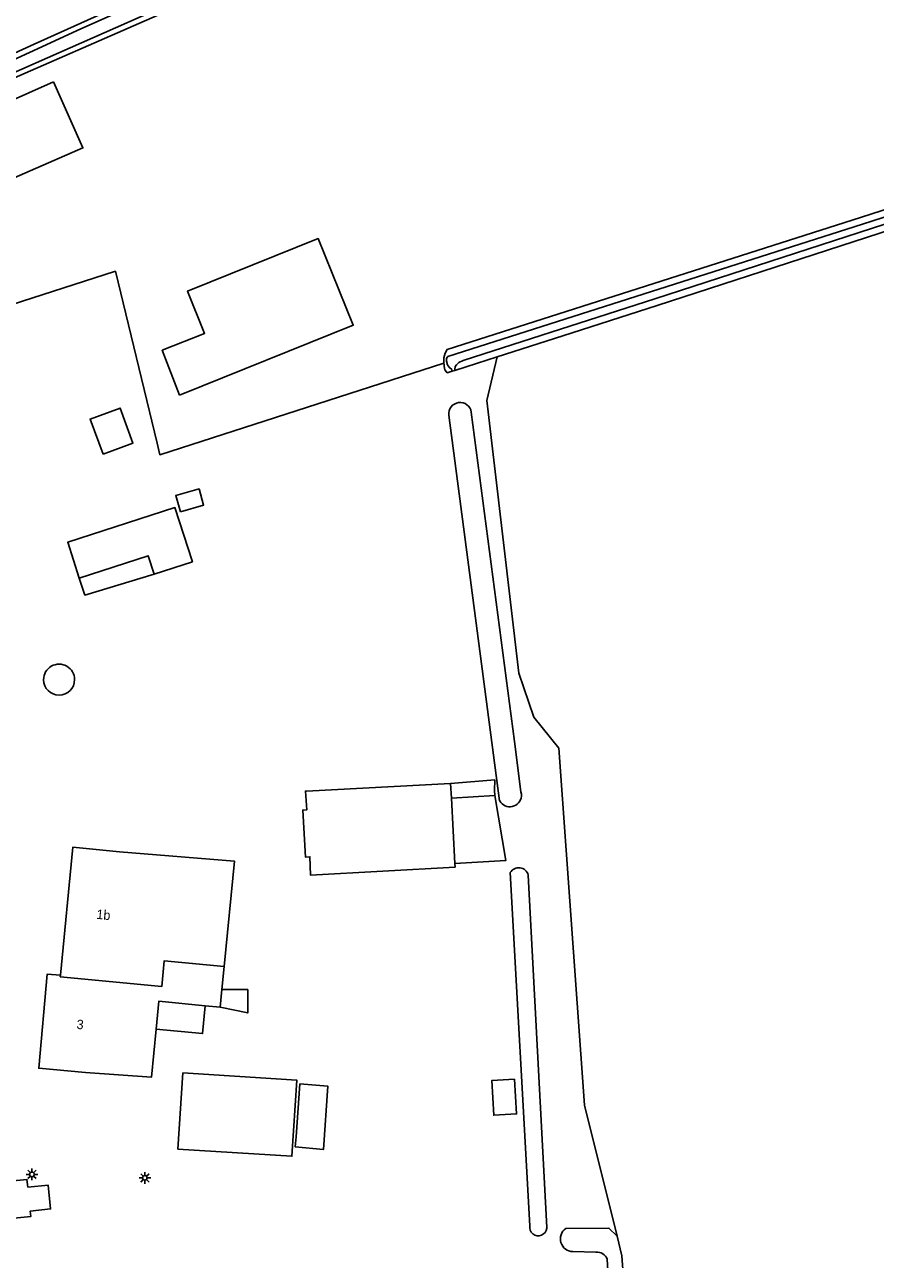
# Model space of a CAD drawing. Extents: x 140000 to 143000, y 403500 to 406000.
# Drawn here: x 140561.8 to 140652.7, y 404354.5 to 404486.5 of the extents above; entities that cross this region are included whole.
import ezdxf

# ---------------------------------------------------------------- set-up
doc = ezdxf.new("R2010")
doc.units = 0
for name, color, linetype in [('gg-anno-huisnummerreeks BGT', 7, 'Continuous'), ('gg-bbg-bijgebouw', 7, 'Continuous'), ('gg-bbg-gedigitaliseerde bijgebouw', 7, 'Continuous'), ('gg-bbg-hoofdgebouw', 7, 'Continuous'), ('gg-bbg-luifel en loopbrug', 7, 'Continuous'), ('gg-bbg-tussenscheiding', 7, 'Continuous'), ('gg-knt-bronhoudergrens', 7, 'Continuous'), ('gg-knt-verharding', 7, 'Continuous'), ('gg-kntw-bovenkant insteek waterloop', 7, 'Continuous'), ('gg-kntw-waterlijn', 7, 'Continuous'), ('gt-bbg-plantopografie pand', 7, 'Continuous'), ('gt-symb-lichtmast', 7, 'Continuous'), ('gx-grn-maaiveld', 7, 'Continuous')]:
    doc.layers.add(name, color=color, linetype=linetype)

# ---------------------------------------------------------------- blocks, each defined once
blk = doc.blocks.new('gt0-LMAST')
at = {"layer": 'gt-symb-lichtmast'}
for p, q in [((-0.18, 0.17), (-0.45, 0.44)), ((-0.01, 0.25), (-0.01, 0.62)), ((0.17, 0.17), (0.44, 0.44)), ((-0.26, 0), (-0.63, 0)), ((-0.18, -0.18), (-0.45, -0.45)), ((-0.01, -0.25), (-0.01, -0.63)), ((0.44, -0.45), (0.17, -0.18)), ((0.24, 0), (0.62, 0))]:
    blk.add_line(p, q, dxfattribs=at)
blk.add_circle((-0.01, 0), 0.25, dxfattribs=at)

msp = doc.modelspace()

# ---------------------------------------------------------------- linework, layer by layer
at = {"layer": 'gg-bbg-bijgebouw'}
for p, q in [((140607.3, 404405.36), (140607.38, 404403.78)), ((140607.38, 404403.78), (140607.75, 404396.79))]:
    msp.add_line(p, q, dxfattribs=at)
for points in [[(140564.83, 404480.4), (140551.92, 404474.66), (140554.95, 404467.67), (140567.98, 404473.32), (140564.83, 404480.4)], [(140570.13, 404440.56), (140568.75, 404444.32), (140571.95, 404445.49), (140573.33, 404441.74), (140570.13, 404440.56)], [(140575.58, 404427.75), (140579.68, 404429.07), (140577.81, 404434.86), (140566.35, 404431.14), (140567.59, 404427.31)], [(140575.58, 404427.75), (140574.95, 404429.71), (140567.59, 404427.31)], [(140607.3, 404405.36), (140591.9, 404404.54), (140591.77, 404404.54), (140591.91, 404402.52), (140591.49, 404402.5), (140591.77, 404397.48), (140592.25, 404397.51), (140592.33, 404395.54), (140607.77, 404396.4), (140607.75, 404396.79)], [(140552.87, 404358.07), (140562.4, 404359.02), (140562.34, 404359.62), (140564.52, 404359.84), (140564.26, 404362.4), (140562.09, 404362.18), (140562, 404363), (140551.8, 404361.98)]]:
    msp.add_lwpolyline(points, dxfattribs=at)
at = {"layer": 'gg-bbg-gedigitaliseerde bijgebouw'}
for points in [[(140578.65, 404374.41), (140590.85, 404373.63), (140590.33, 404365.47), (140578.13, 404366.25), (140578.65, 404374.41)], [(140591.19, 404373.22), (140590.78, 404367.55), (140590.69, 404366.5), (140593.69, 404366.19), (140594.18, 404372.97), (140591.19, 404373.22)], [(140614.14, 404373.72), (140614.35, 404370.01), (140611.9, 404369.87), (140611.69, 404373.58), (140614.14, 404373.72)]]:
    msp.add_lwpolyline(points, dxfattribs=at)
for start, end in [(0.0345, 180.0689), (180.0689, 0.0345)]:
    msp.add_arc((140565.43, 404416.45), 1.66, start, end, dxfattribs=at)
at = {"layer": 'gg-bbg-hoofdgebouw'}
for p, q in [((140583.08, 404385.76), (140582.84, 404383.3)), ((140582.66, 404381.42), (140582.84, 404383.3)), ((140581.06, 404381.57), (140582.66, 404381.42))]:
    msp.add_line(p, q, dxfattribs=at)
for points in [[(140565.57, 404384.84), (140566.9, 404398.53), (140571.88, 404398.04), (140584.17, 404397.04), (140583.08, 404385.76)], [(140565.57, 404384.84), (140564.17, 404384.97), (140563.26, 404374.89), (140568.24, 404374.44), (140575.3, 404373.93), (140575.8, 404379.07)], [(140575.8, 404379.07), (140576.08, 404382.05), (140581.06, 404381.57)]]:
    msp.add_lwpolyline(points, dxfattribs=at)
at = {"layer": 'gg-bbg-luifel en loopbrug'}
msp.add_line((140607.38, 404403.78), (140612.04, 404404.07), dxfattribs=at)
for points in [[(140578.4, 404434.41), (140580.89, 404435.13), (140580.4, 404436.86), (140577.9, 404436.14), (140578.4, 404434.41)], [(140575.58, 404427.75), (140568.2, 404425.49), (140567.59, 404427.31)], [(140607.3, 404405.36), (140612.01, 404405.73), (140611.97, 404404.6), (140612.04, 404404.07)], [(140607.75, 404396.79), (140613.2, 404397.12), (140612.04, 404404.07)], [(140582.66, 404381.42), (140585.6, 404380.8), (140585.6, 404383.3), (140582.84, 404383.3)], [(140575.8, 404379.07), (140580.77, 404378.59), (140581.06, 404381.57)]]:
    msp.add_lwpolyline(points, dxfattribs=at)
at = {"layer": 'gg-bbg-tussenscheiding'}
msp.add_lwpolyline([(140565.57, 404384.84), (140565.55, 404384.67), (140576.41, 404383.62), (140576.68, 404386.38), (140583.08, 404385.76)], dxfattribs=at)
at = {"layer": 'gg-knt-bronhoudergrens'}
msp.add_lwpolyline([(140612.27, 404450.97), (140611.17, 404446.31), (140614.58, 404417.14), (140616.2, 404412.45), (140618.87, 404409.11), (140621.61, 404370.93), (140625.1, 404356.92)], dxfattribs=at)
at = {"layer": 'gg-knt-verharding'}
msp.add_lwpolyline([(140575.92, 404441.74), (140571.45, 404460.14), (140555.84, 404455.11), (140525.94, 404445.69)], dxfattribs=at)
at = {"layer": 'gg-kntw-bovenkant insteek waterloop'}
for p, q in [((140612.27, 404450.97), (140619.28, 404453.22)), ((140607.1, 404444.74), (140612.54, 404403.48)), ((140613.68, 404395.81), (140615.76, 404358.05)), ((140625.1, 404356.92), (140625.62, 404354.81)), ((140622.84, 404355.23), (140620.37, 404355.28)), ((140624.04, 404354.46), (140626.93, 404300.62)), ((140629.11, 404300.61), (140625.62, 404354.81))]:
    msp.add_line(p, q, dxfattribs=at)
for points in [[(140666.62, 404527.97), (140659.46, 404524.87), (140640.73, 404516.48), (140623.81, 404509.02), (140621.4, 404508.04), (140620.12, 404507.42), (140618.62, 404506.41), (140617.55, 404505.74), (140597.26, 404497.06), (140576.48, 404487.74), (140557.53, 404479.45), (140535.75, 404469.66), (140527.71, 404465.66)], [(140621.8, 404510.82), (140612.07, 404506.52), (140586.99, 404495.35), (140562.75, 404484.41), (140542.11, 404474.98), (140526.29, 404467.87)], [(140619.28, 404453.22), (140629.37, 404456.46), (140684.03, 404474.21), (140712.94, 404483.56)], [(140609.51, 404445.07), (140614.11, 404409.84), (140614.82, 404404.45), (140614.86, 404404.22), (140614.86, 404403.98)], [(140617.59, 404357.78), (140617.6, 404357.86), (140615.58, 404395.55)], [(140625.1, 404356.92), (140624.23, 404357.8), (140619.6, 404357.75)]]:
    msp.add_lwpolyline(points, dxfattribs=at)
for centre, radius, start, end in [((140608.31, 404444.89), 1.21, 8.5353, 187.0971), ((140613.62, 404404.11), 1.25, 210.479, 354.0915), ((140614.58, 404395.3), 1.04, 14.246, 150.2452), ((140616.67, 404357.9), 0.926, 170.6834, 352.6101), ((140620.39, 404356.64), 1.36, 125.2653, 269.292), ((140622.94, 404354.06), 1.17, 19.7526, 94.8926)]:
    msp.add_arc(centre, radius, start, end, dxfattribs=at)
at = {"layer": 'gg-kntw-waterlijn'}
msp.add_lwpolyline([(140577.84, 404488.98), (140557.79, 404480.15), (140541.28, 404472.97), (140530.56, 404467.57), (140528.22, 404466.34), (140526.13, 404465.91), (140525.68, 404465.98), (140525.31, 404466.11), (140525.2, 404466.39), (140525.27, 404466.69), (140525.47, 404466.87), (140528.4, 404468.09), (140545.77, 404475.93), (140567.76, 404486.05), (140593.6, 404497.59)], dxfattribs=at)
at = {"layer": 'gt-bbg-plantopografie pand'}
msp.add_lwpolyline([(140578.32, 404446.89), (140596.88, 404454.36), (140593.14, 404463.63), (140579.17, 404458.01), (140580.99, 404453.49), (140576.47, 404451.68), (140578.32, 404446.89)], dxfattribs=at)
at = {"layer": 'gx-grn-maaiveld'}
msp.add_line((140607.76, 404449.53), (140607.47, 404449.43), dxfattribs=at)
for points in [[(140606.58, 404450.3), (140606.57, 404450.86), (140606.71, 404451.38), (140606.92, 404451.76), (140651.12, 404465.88), (140713.05, 404485.87)], [(140607.47, 404449.43), (140607.42, 404449.61), (140607.17, 404449.83), (140607, 404450.07), (140606.95, 404450.14), (140606.87, 404450.52), (140606.87, 404450.79), (140607, 404451), (140651.35, 404465.16), (140713.01, 404485.07)], [(140607.76, 404449.53), (140607.74, 404449.62), (140607.78, 404449.93), (140607.93, 404450.14), (140608.17, 404450.36), (140608.64, 404450.6), (140608.74, 404450.63), (140619.05, 404453.94), (140629.14, 404457.18), (140683.8, 404474.93), (140712.98, 404484.36)], [(140612.27, 404450.97), (140608.97, 404449.92), (140607.76, 404449.53)], [(140606.58, 404450.3), (140576.2, 404440.5), (140575.92, 404441.74)], [(140607.47, 404449.43), (140606.94, 404449.27), (140606.67, 404449.58), (140606.62, 404449.95), (140606.59, 404450.17), (140606.58, 404450.3)]]:
    msp.add_lwpolyline(points, dxfattribs=at)

# ---------------------------------------------------------------- block references
at = {"layer": 'gt-symb-lichtmast'}
for p in [(140562.54, 404363.54), (140574.61, 404363.17)]:
    msp.add_blockref('gt0-LMAST', p, dxfattribs=at)

# ---------------------------------------------------------------- texts
at = {"layer": 'gg-anno-huisnummerreeks BGT'}
for s, rotation, p in [('1b', 354.4, (140569.39, 404390.88)), ('3', 354.8, (140567.27, 404379.11))]:
    msp.add_text(s, height=1, rotation=rotation, dxfattribs=at).set_placement(p)

doc.saveas('drawing.dxf')
